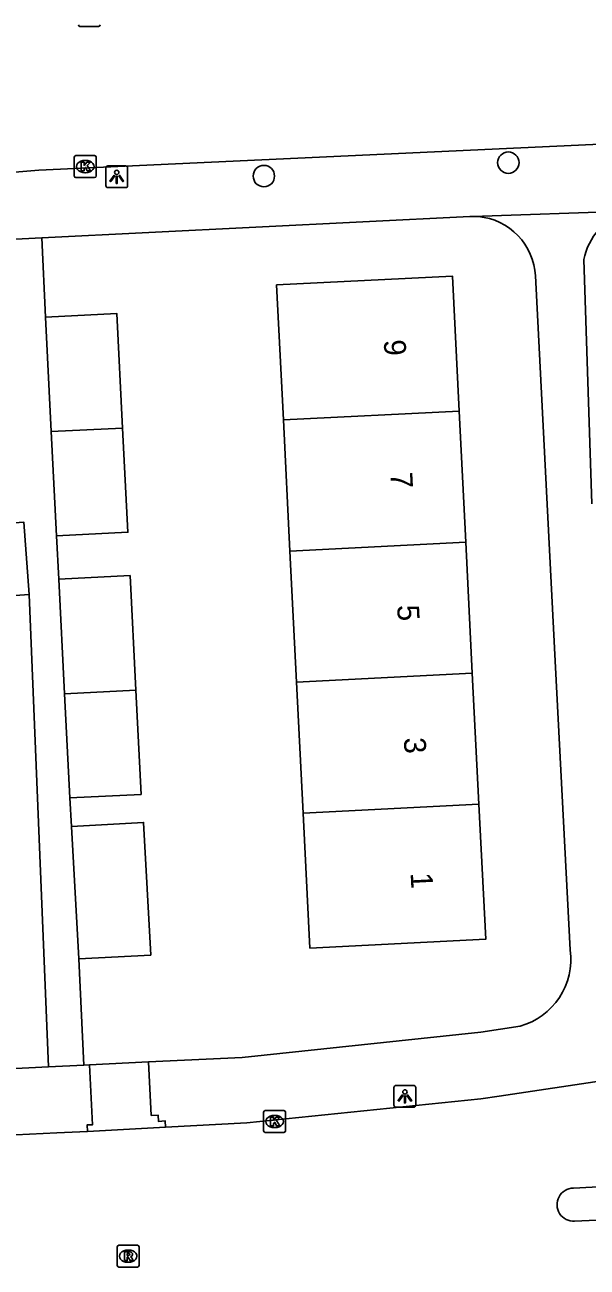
# Model space of a CAD drawing. Extents: x 161084 to 161928, y 385355 to 386522.
# Drawn here: x 161585.8 to 161611.5, y 385753.7 to 385810.5 of the extents above; entities that cross this region are included whole.
import ezdxf

# ---------------------------------------------------------------- set-up
doc = ezdxf.new("R2010")
doc.units = 0
for name, color, linetype in [('IMGEO_Boom', 7, 'Continuous'), ('IMGEO_Kolk', 7, 'Continuous'), ('IMGEO_Lichtpunt', 7, 'Continuous'), ('IMGEO_Pand', 7, 'Continuous'), ('IMGEO_Pand_nummerreeks', 7, 'Continuous'), ('IMGEO_Rijbaan_lokaal_gesloten', 7, 'Continuous'), ('IMGEO_Rijbaan_lokaal_open', 7, 'Continuous'), ('IMGEO_Rioolput', 7, 'Continuous'), ('IMGEO_Voetpad_open', 7, 'Continuous')]:
    doc.layers.add(name, color=color, linetype=linetype)

msp = doc.modelspace()

# ---------------------------------------------------------------- linework, layer by layer
at = {"layer": 'IMGEO_Boom'}
for centre in [(161607.869, 385804.239), (161596.686, 385803.623)]:
    msp.add_circle(centre, 0.489, dxfattribs=at)
at = {"layer": 'IMGEO_Kolk'}
for p, q in [((161589.126, 385810.465), (161588.274, 385810.465)), ((161588.015, 385803.634), (161588.015, 385804.486)), ((161588.09, 385804.56), (161588.942, 385804.56)), ((161588.503, 385804.34), (161588.528, 385804.34)), ((161589.016, 385804.486), (161589.016, 385803.634)), ((161588.526, 385803.78), (161588.501, 385803.78)), ((161588.942, 385803.56), (161588.09, 385803.56)), ((161596.676, 385759.975), (161596.676, 385760.827)), ((161596.751, 385760.901), (161597.603, 385760.901)), ((161597.164, 385760.681), (161597.189, 385760.681)), ((161597.677, 385760.827), (161597.677, 385759.975)), ((161597.187, 385760.121), (161597.162, 385760.121)), ((161597.603, 385759.901), (161596.751, 385759.901))]:
    msp.add_line(p, q, dxfattribs=at)
for points in [[(161589.126, 385810.465), (161588.274, 385810.465)], [(161588.015, 385803.634), (161588.015, 385804.486)], [(161588.09, 385804.56), (161588.942, 385804.56)], [(161589.016, 385804.486), (161589.016, 385803.634)], [(161588.336, 385804.26), (161588.459, 385804.26), (161588.459, 385804.109), (161588.589, 385804.26), (161588.753, 385804.26), (161588.607, 385804.109), (161588.76, 385803.86), (161588.608, 385803.86), (161588.523, 385804.024), (161588.459, 385803.957), (161588.459, 385803.86), (161588.336, 385803.86), (161588.336, 385804.26)], [(161588.942, 385803.56), (161588.09, 385803.56)], [(161596.676, 385759.975), (161596.676, 385760.827)], [(161596.751, 385760.901), (161597.603, 385760.901)], [(161596.997, 385760.601), (161597.12, 385760.601), (161597.12, 385760.45), (161597.25, 385760.601), (161597.414, 385760.601), (161597.268, 385760.45), (161597.421, 385760.201), (161597.269, 385760.201), (161597.184, 385760.365), (161597.12, 385760.298), (161597.12, 385760.201), (161596.997, 385760.201), (161596.997, 385760.601)], [(161597.677, 385760.827), (161597.677, 385759.975)], [(161597.603, 385759.901), (161596.751, 385759.901)]]:
    msp.add_lwpolyline(points, dxfattribs=at)
for centre, start, end in [((161588.276, 385810.541), 181.552, 268.448), ((161588.276, 385810.541), 181.552, 268.448), ((161589.124, 385810.541), 271.552, 358.448), ((161589.124, 385810.541), 271.552, 358.448), ((161588.092, 385804.484), 91.552, 178.448), ((161588.092, 385804.484), 91.552, 178.448), ((161588.94, 385804.484), 1.552, 88.448), ((161588.94, 385804.484), 1.552, 88.448), ((161588.092, 385803.636), 181.552, 268.448), ((161588.092, 385803.636), 181.552, 268.448), ((161588.94, 385803.636), 271.552, 358.448), ((161588.94, 385803.636), 271.552, 358.448), ((161596.753, 385760.825), 91.552, 178.448), ((161596.753, 385760.825), 91.552, 178.448), ((161597.601, 385760.825), 1.552, 88.448), ((161597.601, 385760.825), 1.552, 88.448), ((161596.753, 385759.977), 181.552, 268.448), ((161596.753, 385759.977), 181.552, 268.448), ((161597.601, 385759.977), 271.552, 358.448), ((161597.601, 385759.977), 271.552, 358.448)]:
    msp.add_arc(centre, 0.0765, start, end, dxfattribs=at)
for centre, major_axis, ratio, start_param, end_param in [((161588.502, 385804.06), (-0.387, 0.002), 0.722429, 4.712389, 7.853982), ((161588.527, 385804.06), (-0.39, 0.002), 0.717154, 1.570796, 4.712389), ((161597.163, 385760.401), (-0.387, 0.002), 0.722429, 4.712389, 7.853982), ((161597.188, 385760.401), (-0.39, 0.002), 0.717154, 1.570796, 4.712389)]:
    msp.add_ellipse(centre, major_axis=major_axis, ratio=ratio, start_param=start_param, end_param=end_param, dxfattribs=at)
at = {"layer": 'IMGEO_Lichtpunt'}
for p, q in [((161589.459, 385803.997), (161589.459, 385803.19)), ((161589.459, 385803.997), (161589.459, 385803.19)), ((161590.361, 385804.092), (161589.553, 385804.092)), ((161590.361, 385804.092), (161589.553, 385804.092)), ((161590.455, 385803.19), (161590.455, 385803.997)), ((161590.455, 385803.19), (161590.455, 385803.997)), ((161589.553, 385803.096), (161590.361, 385803.096)), ((161589.553, 385803.096), (161590.361, 385803.096)), ((161602.638, 385761.955), (161602.638, 385761.148)), ((161602.638, 385761.955), (161602.638, 385761.148)), ((161603.54, 385762.05), (161602.732, 385762.05)), ((161603.54, 385762.05), (161602.732, 385762.05)), ((161603.634, 385761.148), (161603.634, 385761.955)), ((161603.634, 385761.148), (161603.634, 385761.955)), ((161602.732, 385761.054), (161603.54, 385761.054)), ((161602.732, 385761.054), (161603.54, 385761.054))]:
    msp.add_line(p, q, dxfattribs=at)
for points in [[(161589.833, 385803.661), (161589.872, 385803.633), (161589.684, 385803.371), (161589.646, 385803.398), (161589.833, 385803.661)], [(161589.935, 385803.613), (161589.982, 385803.613), (161589.982, 385803.291), (161589.935, 385803.291), (161589.935, 385803.613)], [(161590.045, 385803.633), (161590.083, 385803.66), (161590.27, 385803.398), (161590.231, 385803.37), (161590.045, 385803.633)], [(161603.012, 385761.619), (161603.051, 385761.591), (161602.863, 385761.329), (161602.825, 385761.356), (161603.012, 385761.619)], [(161603.114, 385761.571), (161603.161, 385761.571), (161603.161, 385761.249), (161603.114, 385761.249), (161603.114, 385761.571)], [(161603.224, 385761.591), (161603.262, 385761.618), (161603.449, 385761.356), (161603.41, 385761.328), (161603.224, 385761.591)]]:
    msp.add_lwpolyline(points, dxfattribs=at)
for centre in [(161589.958, 385803.795), (161603.137, 385761.753)]:
    msp.add_circle(centre, 0.0994, dxfattribs=at)
for centre, start, end in [((161589.553, 385803.997), 90, 180), ((161589.553, 385803.997), 90, 180), ((161590.361, 385803.997), 0, 90), ((161590.361, 385803.997), 0, 90), ((161589.553, 385803.19), 180, 270), ((161589.553, 385803.19), 180, 270), ((161590.361, 385803.19), 270, 0), ((161590.361, 385803.19), 270, 360), ((161602.732, 385761.955), 90, 180), ((161602.732, 385761.955), 90, 180), ((161603.54, 385761.955), 0, 90), ((161603.54, 385761.955), 0, 90), ((161602.732, 385761.148), 180, 270), ((161602.732, 385761.148), 180, 270), ((161603.54, 385761.148), 270, 0), ((161603.54, 385761.148), 270, 360)]:
    msp.add_arc(centre, 0.0946, start, end, dxfattribs=at)
at = {"layer": 'IMGEO_Pand'}
for points in [[(161597.578, 385792.475), (161597.267, 385798.645), (161605.308, 385799.049), (161605.619, 385792.879)], [(161586.697, 385797.175), (161589.964, 385797.34), (161590.227, 385792.106)], [(161586.96, 385791.942), (161586.697, 385797.175)], [(161597.578, 385792.475), (161605.619, 385792.879)], [(161597.879, 385786.483), (161597.578, 385792.475)], [(161605.619, 385792.879), (161605.92, 385786.887)], [(161586.96, 385791.942), (161590.227, 385792.106)], [(161587.2, 385787.177), (161586.96, 385791.942)], [(161590.227, 385792.106), (161590.467, 385787.341), (161587.2, 385787.177)], [(161580.616, 385787.43), (161585.708, 385787.795), (161585.945, 385784.489)], [(161585.945, 385784.489), (161580.853, 385784.124), (161580.616, 385787.43)], [(161605.92, 385786.887), (161597.879, 385786.483)], [(161605.92, 385786.887), (161606.222, 385780.895)], [(161598.181, 385780.491), (161597.879, 385786.483)], [(161587.3, 385785.191), (161590.567, 385785.356), (161590.83, 385780.122)], [(161587.563, 385779.958), (161587.3, 385785.191)], [(161598.181, 385780.491), (161606.222, 385780.895)], [(161598.482, 385774.498), (161598.181, 385780.491)], [(161606.222, 385780.895), (161606.524, 385774.902)], [(161590.83, 385780.122), (161587.563, 385779.958)], [(161587.803, 385775.193), (161587.563, 385779.958)], [(161590.83, 385780.122), (161591.07, 385775.357), (161587.803, 385775.193)], [(161606.524, 385774.902), (161606.834, 385768.734), (161598.793, 385768.329), (161598.482, 385774.498)], [(161606.524, 385774.902), (161598.482, 385774.498)], [(161587.892, 385773.895), (161591.184, 385774.073), (161591.513, 385768.01), (161588.222, 385767.831)], [(161588.222, 385767.831), (161587.892, 385773.895)]]:
    msp.add_lwpolyline(points, dxfattribs=at)
at = {"layer": 'IMGEO_Rijbaan_lokaal_gesloten'}
for points in [[(161592.192, 385760.139), (161595.909, 385760.336), (161606.605, 385761.434), (161607.456, 385761.563), (161617.417, 385763.057), (161617.912, 385763.129), (161618.399, 385763.244), (161618.873, 385763.403), (161619.331, 385763.603)], [(161588.617, 385759.949), (161592.192, 385760.139)], [(161534.012, 385757.077), (161559.087, 385758.539), (161575.415, 385759.247), (161583.446, 385759.696), (161587.221, 385759.881), (161588.617, 385759.949)], [(161612.837, 385757.454), (161610.843, 385757.36)], [(161610.9, 385755.841), (161612.924, 385755.941)]]:
    msp.add_lwpolyline(points, dxfattribs=at)
msp.add_arc((161610.858, 385756.6), 0.76, 91.1012, 273.1968, dxfattribs=at)
at = {"layer": 'IMGEO_Rijbaan_lokaal_open'}
msp.add_lwpolyline([(161351.902, 385854.625), (161361.37, 385852.342), (161406.44, 385841.585), (161439.496, 385833.681), (161487.09, 385822.28), (161490.645, 385821.437), (161540.178, 385809.69), (161553.334, 385806.533), (161560.913, 385804.952), (161564.397, 385804.459), (161572.843, 385803.627), (161581.329, 385803.552), (161583.838, 385803.676), (161586.385, 385803.89), (161616.338, 385805.286)], dxfattribs=at)
at = {"layer": 'IMGEO_Rioolput'}
for p, q in [((161589.979, 385753.816), (161589.979, 385754.668)), ((161590.054, 385754.742), (161590.906, 385754.742)), ((161590.467, 385754.522), (161590.492, 385754.522)), ((161590.98, 385754.668), (161590.98, 385753.816)), ((161590.49, 385753.962), (161590.465, 385753.962)), ((161590.906, 385753.742), (161590.054, 385753.742))]:
    msp.add_line(p, q, dxfattribs=at)
for points in [[(161589.979, 385753.816), (161589.979, 385754.668)], [(161590.054, 385754.742), (161590.906, 385754.742)], [(161590.568, 385754.44), (161590.316, 385754.442), (161590.316, 385754.042)], [(161590.494, 385754.361), (161590.44, 385754.361), (161590.44, 385754.28)], [(161590.98, 385754.668), (161590.98, 385753.816)], [(161590.316, 385754.042), (161590.44, 385754.042), (161590.44, 385754.204), (161590.451, 385754.204)], [(161590.44, 385754.28), (161590.492, 385754.28)], [(161590.498, 385754.175), (161590.569, 385754.042), (161590.709, 385754.042), (161590.644, 385754.168)], [(161590.906, 385753.742), (161590.054, 385753.742)]]:
    msp.add_lwpolyline(points, dxfattribs=at)
for centre, radius, start, end in [((161590.056, 385754.666), 0.0765, 91.552, 178.448), ((161590.056, 385754.666), 0.0765, 91.552, 178.448), ((161590.5, 385754.265), 0.0964, 77.0061, 93.1865), ((161590.514, 385754.322), 0.0378, 276.6634, 79.6772), ((161590.567, 385754.33), 0.109, 350.3612, 89.416), ((161590.565, 385754.33), 0.112, 277.5842, 350.9817), ((161590.904, 385754.666), 0.0765, 1.552, 88.448), ((161590.904, 385754.666), 0.0765, 1.552, 88.448), ((161590.056, 385753.818), 0.0765, 181.552, 268.448), ((161590.056, 385753.818), 0.0765, 181.552, 268.448), ((161590.45, 385754.151), 0.0533, 26.0293, 88.6989), ((161590.476, 385754.469), 0.19, 274.7715, 282.9687), ((161590.549, 385754.115), 0.108, 29.5134, 73.7905), ((161590.904, 385753.818), 0.0765, 271.552, 358.448), ((161590.904, 385753.818), 0.0765, 271.552, 358.448)]:
    msp.add_arc(centre, radius, start, end, dxfattribs=at)
for centre, major_axis, ratio, start_param, end_param in [((161590.466, 385754.242), (-0.387, 0.002), 0.722429, 4.712389, 7.853982), ((161590.491, 385754.242), (-0.39, 0.002), 0.717154, 1.570796, 4.712389)]:
    msp.add_ellipse(centre, major_axis=major_axis, ratio=ratio, start_param=start_param, end_param=end_param, dxfattribs=at)
at = {"layer": 'IMGEO_Voetpad_open'}
for points in [[(161606.247, 385801.783), (161606.104, 385801.779), (161586.527, 385800.803)], [(161591.406, 385763.129), (161595.688, 385763.331), (161606.616, 385764.485), (161608.407, 385764.757), (161608.677, 385764.845), (161608.937, 385764.957), (161609.187, 385765.092), (161609.423, 385765.248), (161609.645, 385765.425), (161609.85, 385765.621), (161610.036, 385765.835), (161610.203, 385766.064), (161610.348, 385766.308), (161610.472, 385766.563), (161610.572, 385766.828), (161610.647, 385767.102), (161610.699, 385767.381), (161610.725, 385767.663), (161610.725, 385767.946), (161610.701, 385768.229), (161610.698, 385768.248), (161610.026, 385781.153), (161609.107, 385799.067), (161609.083, 385799.322), (161609.035, 385799.573), (161608.966, 385799.819), (161608.875, 385800.059), (161608.763, 385800.289), (161608.631, 385800.508), (161608.479, 385800.714), (161608.31, 385800.906), (161608.125, 385801.082), (161607.924, 385801.241), (161607.71, 385801.382), (161607.485, 385801.502), (161607.249, 385801.602), (161607.006, 385801.681), (161606.756, 385801.737), (161606.503, 385801.771), (161606.247, 385801.783)], [(161613.28, 385802.014), (161606.247, 385801.783)], [(161586.527, 385800.803), (161585.028, 385800.728)], [(161586.527, 385800.803), (161586.697, 385797.175)], [(161611.687, 385788.641), (161611.32, 385799.81)], [(161587.2, 385787.177), (161587.3, 385785.191)], [(161586.836, 385762.898), (161585.945, 385784.489)], [(161587.803, 385775.193), (161587.892, 385773.895)], [(161588.222, 385767.831), (161588.446, 385762.979)], [(161533.793, 385761.193), (161533.843, 385760.213), (161586.836, 385762.898)], [(161586.836, 385762.898), (161588.446, 385762.979)], [(161588.446, 385762.979), (161588.705, 385762.992)], [(161588.705, 385762.992), (161588.85, 385760.254), (161588.602, 385760.241), (161588.617, 385759.949)], [(161588.705, 385762.992), (161591.406, 385763.129)], [(161592.192, 385760.139), (161592.176, 385760.425), (161591.86, 385760.408), (161591.845, 385760.692), (161591.536, 385760.676), (161591.406, 385763.129)]]:
    msp.add_lwpolyline(points, dxfattribs=at)
msp.add_arc((161614.206, 385799.217), 2.946, 108.3146, 168.3925, dxfattribs=at)

# ---------------------------------------------------------------- texts
at = {"layer": 'IMGEO_Pand_nummerreeks'}
for s, p in [('9', (161602.17, 385796.128)), ('7', (161602.475, 385790.065)), ('5', (161602.781, 385784.002)), ('3', (161603.086, 385777.939)), ('1', (161603.397, 385771.762))]:
    msp.add_text(s, height=1, rotation=272.8817, dxfattribs=at).set_placement(p)

doc.saveas('drawing.dxf')
